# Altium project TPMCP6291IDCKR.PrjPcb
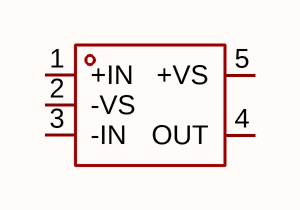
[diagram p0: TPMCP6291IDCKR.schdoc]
1 sheet, 1 parts. Net scope: global (net labels, ports and power ports of the same name join across sheets).

## Sheet TPMCP6291IDCKR.schdoc
size 127 x 101 mm

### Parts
U?  tpmcp6291idckr  [SOT-23-5_L2.9-W1.6-P0.95-LS2.8-BL]  (value not drawn)

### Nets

Not connected (* = marked no-connect by the designer): U? 1(+IN) 2(-VS) 3(-IN) 4(OUT) 5(+VS)

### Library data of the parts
U? = tpmcp6291idckr: Manufacturer: TECH PUBLIC(台舟); AddInBom: yes; ModelId: 018c57e721114987ae90467fe9f1d259; ModelTransform: 114.96,110.236,0,0,0,0,0,0,0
